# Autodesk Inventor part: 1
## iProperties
Created: 2012-03
Part Number: 1
Document SubType Name: Modeling
Designer: Administrator
Density: 7.85 g/cm^3
Material: Steel
Mass: 45.9281 g
Surface Area: 71.525 cm^2
Volume: 5.85071 cm^3
Translation Standard: STEP AP203
FileName: //expscmdclustefs.cadenas.external/client_exchange/iodir/jobs/output/wkb42693478_no0/STEP/208_9001__24208_90010__2_03.stp
PostProcessor: Build: 236a, Release: 2009 RTM - Date: Fri 02/22/2008
Sent Units: MM
Uncertainty: 1.0000000000000002e-06
Author: Administrator
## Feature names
1. Base1
